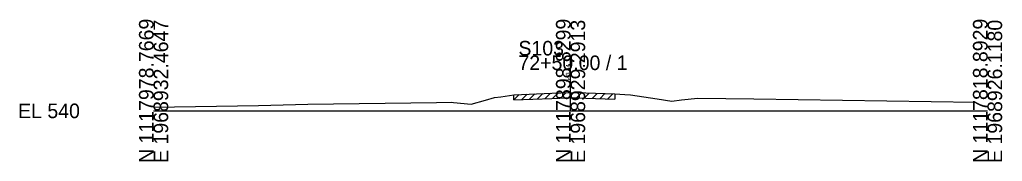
# Model space of a CAD drawing. Extents: x -26 to 163, y -10 to 45020.
# Drawn here: x -25.7 to 162.8, y 31490.3 to 31517.5 of the extents above; entities that cross this region are included whole.
import ezdxf

# ---------------------------------------------------------------- set-up
doc = ezdxf.new("R2010")
doc.units = 0
for name, color, linetype in [('RD_GPK_XS_Cell', 7, 'Continuous'), ('RD_XS_ExGround', 7, 'Continuous'), ('RD_XS_ExPaveRet', 7, 'Continuous'), ('RD_XS_TX_Elev_EX', 7, 'Continuous')]:
    doc.layers.add(name, color=color, linetype=linetype)

msp = doc.modelspace()

# ---------------------------------------------------------------- linework, layer by layer
at = {"layer": 'RD_GPK_XS_Cell'}
for p, q in [((80, 31500), (80, 31510.63)), ((0, 31500), (80, 31500)), ((80, 31500), (160, 31500))]:
    msp.add_line(p, q, dxfattribs=at)
at = {"layer": 'RD_XS_ExGround'}
for p, q in [((60.95, 31501.26), (63.66, 31502.04)), ((63.66, 31502.04), (65.42, 31502.54)), ((65.42, 31502.54), (66.62, 31502.72)), ((66.62, 31502.72), (69.13, 31503.11)), ((69.13, 31503.11), (76.38, 31503.4)), ((76.38, 31503.4), (80.08, 31503.54)), ((80.08, 31503.54), (82.92, 31503.44)), ((82.92, 31503.44), (88.47, 31503.24)), ((88.47, 31503.24), (90.43, 31503.15)), ((90.43, 31503.15), (91.49, 31503.1)), ((91.49, 31503.1), (96.62, 31502.31)), ((96.62, 31502.31), (99.43, 31501.87)), ((99.43, 31501.87), (101.26, 31502.09)), ((101.26, 31502.09), (104.41, 31502.45)), ((104.41, 31502.45), (115.13, 31502.31)), ((115.13, 31502.31), (157.72, 31501.67)), ((0, 31500.73), (20.11, 31501.05)), ((20.11, 31501.05), (29.58, 31501.27)), ((29.58, 31501.27), (54.25, 31501.61)), ((54.25, 31501.61), (57.15, 31501.64)), ((57.15, 31501.64), (57.57, 31501.61)), ((57.57, 31501.61), (60.95, 31501.26))]:
    msp.add_line(p, q, dxfattribs=at)
at = {"layer": 'RD_XS_ExPaveRet'}
for p, q in [((69.13, 31502.11), (70.17, 31503.15)), ((69.13, 31502.11), (69.13, 31503.11)), ((69.13, 31502.11), (76.38, 31502.4)), ((70.63, 31502.17), (71.67, 31503.21)), ((72.13, 31502.23), (73.17, 31503.27)), ((73.63, 31502.29), (74.67, 31503.33)), ((75.13, 31502.35), (76.17, 31503.39)), ((76.38, 31502.4), (80.08, 31502.54)), ((76.63, 31502.41), (77.67, 31503.45)), ((78.13, 31502.47), (79.17, 31503.51)), ((79.63, 31502.53), (80.62, 31503.52)), ((80.08, 31502.54), (82.92, 31502.44)), ((81.13, 31502.51), (82.09, 31503.47)), ((82.63, 31502.45), (83.59, 31503.42)), ((82.92, 31502.44), (88.47, 31502.24)), ((84.13, 31502.4), (85.09, 31503.36)), ((85.63, 31502.34), (86.59, 31503.31)), ((87.13, 31502.29), (88.09, 31503.26)), ((88.47, 31503.24), (88.47, 31502.24))]:
    msp.add_line(p, q, dxfattribs=at)

# ---------------------------------------------------------------- texts
at = {"layer": 'RD_GPK_XS_Cell'}
for s, p in [('N 1117978.7669', (0, 31490)), ('E 1968932.4647', (2.8, 31490)), ('N 1117898.8299', (80, 31490)), ('E 1968929.2913', (82.8, 31490)), ('N 1117818.8929', (160, 31490)), ('E 1968926.1180', (162.8, 31490))]:
    msp.add_text(s, height=2.8, rotation=90, dxfattribs=at).set_placement(p)
for s, p in [('S103', (70, 31510.63)), ('72+50.00 / 1', (70, 31507.83)), ('EL 540', (-26, 31498.6))]:
    msp.add_text(s, height=2.8, dxfattribs=at).set_placement(p)
at = {"layer": 'RD_XS_TX_Elev_EX'}
msp.add_text('543.54', height=0.8, rotation=90, dxfattribs=at).set_placement((79.9, 31505.54))

doc.saveas('drawing.dxf')
